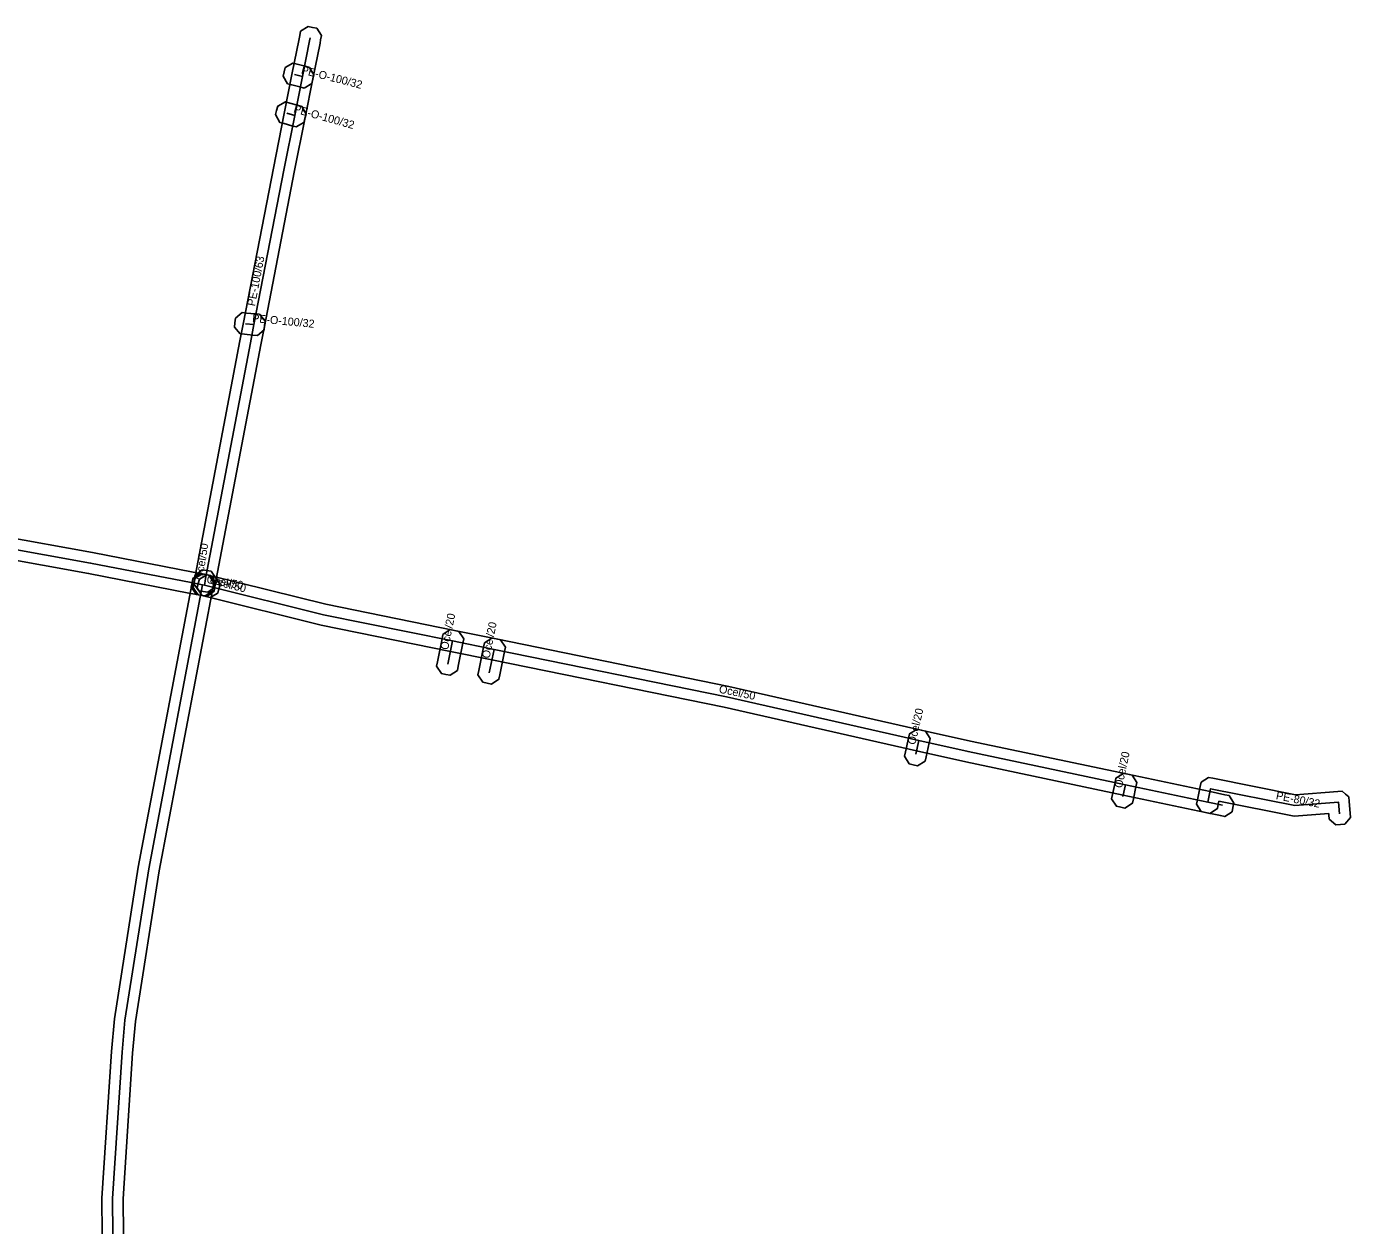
# Model space of a CAD drawing. Extents: x -569373 to -565022, y -1135090 to -1131496.
# Drawn here: x -566970.9 to -566846.8, y -1134085 to -1133972.5 of the extents above; entities that cross this region are included whole.
import ezdxf

# ---------------------------------------------------------------- set-up
doc = ezdxf.new("R2010")
doc.units = 0
for name, color, linetype in [('1', 7, 'Continuous'), ('24', 7, 'Continuous'), ('30', 7, 'Continuous')]:
    doc.layers.add(name, color=color, linetype=linetype)

msp = doc.modelspace()

# ---------------------------------------------------------------- linework, layer by layer
at = {"layer": '1'}
for points in [[(-566955.252, -1134024.771), (-566955.187, -1134024.362), (-566955.139, -1134024.062), (-566955.096, -1134023.897), (-566950.922, -1134001.992), (-566950.59, -1134000.272), (-566947.791, -1133985.798), (-566946.772, -1133980.668), (-566946.047, -1133977.022), (-566945.38, -1133973.671), (-566945.319, -1133973.377), (-566945.235, -1133972.971), (-566944.543, -1133972.517), (-566944.137, -1133972.601), (-566943.731, -1133972.685), (-566943.277, -1133973.377), (-566943.361, -1133973.783), (-566943.42, -1133974.069), (-566944.085, -1133977.412), (-566944.81, -1133981.058), (-566945.829, -1133986.182), (-566948.626, -1134000.652), (-566948.958, -1134002.368), (-566953.144, -1134024.343), (-566953.181, -1134024.478), (-566953.213, -1134024.678), (-566953.278, -1134025.087), (-566953.949, -1134025.572), (-566954.358, -1134025.507), (-566954.767, -1134025.442)], [(-566944.913, -1133978.289), (-566945.314, -1133978.186), (-566946.064, -1133977.994), (-566946.465, -1133977.891), (-566946.888, -1133977.178), (-566946.785, -1133976.777), (-566946.682, -1133976.376), (-566945.969, -1133975.953), (-566945.568, -1133976.056), (-566944.818, -1133976.248), (-566944.417, -1133976.351), (-566943.994, -1133977.064), (-566944.097, -1133977.465), (-566944.2, -1133977.866)], [(-566945.663, -1133981.938), (-566946.062, -1133981.826), (-566946.791, -1133981.621), (-566947.189, -1133981.509), (-566947.595, -1133980.786), (-566947.483, -1133980.387), (-566947.371, -1133979.989), (-566946.648, -1133979.583), (-566946.249, -1133979.695), (-566945.52, -1133979.9), (-566945.122, -1133980.012), (-566944.716, -1133980.735), (-566944.828, -1133981.134), (-566944.94, -1133981.532)], [(-566949.29, -1134001.497), (-566949.703, -1134001.458), (-566950.491, -1134001.383), (-566950.903, -1134001.344), (-566951.431, -1134000.705), (-566951.392, -1134000.292), (-566951.353, -1133999.88), (-566950.714, -1133999.352), (-566950.301, -1133999.391), (-566949.513, -1133999.466), (-566949.101, -1133999.505), (-566948.573, -1134000.144), (-566948.612, -1134000.557), (-566948.651, -1134000.969)], [(-566954.664, -1134023.813), (-566954.256, -1134023.885), (-566954.086, -1134023.915), (-566953.678, -1134023.987), (-566953.203, -1134024.666), (-566953.275, -1134025.074), (-566953.347, -1134025.482), (-566954.026, -1134025.957), (-566954.434, -1134025.885), (-566954.604, -1134025.855), (-566955.012, -1134025.783), (-566955.487, -1134025.104), (-566955.415, -1134024.696), (-566955.343, -1134024.288)], [(-566954.419, -1134023.829), (-566954.017, -1134023.93), (-566953.617, -1134024.03), (-566953.215, -1134024.13), (-566952.789, -1134024.841), (-566952.89, -1134025.243), (-566952.99, -1134025.645), (-566953.701, -1134026.071), (-566954.103, -1134025.97), (-566954.503, -1134025.87), (-566954.905, -1134025.77), (-566955.331, -1134025.059), (-566955.23, -1134024.657), (-566955.13, -1134024.255)], [(-566955.313, -1134025.153), (-566955.248, -1134024.744), (-566955.188, -1134024.364), (-566955.123, -1134023.955), (-566954.453, -1134023.467), (-566954.044, -1134023.532), (-566953.635, -1134023.597), (-566953.147, -1134024.267), (-566953.212, -1134024.676), (-566953.272, -1134025.056), (-566953.337, -1134025.465), (-566954.007, -1134025.953), (-566954.416, -1134025.888), (-566954.825, -1134025.823)], [(-566954.021, -1134023.93), (-566953.619, -1134024.03), (-566942.859, -1134026.704), (-566930.801, -1134029.16), (-566926.91, -1134029.95), (-566905.109, -1134034.402), (-566887.059, -1134038.495), (-566882.457, -1134039.533), (-566867.714, -1134042.642), (-566859.994, -1134044.271), (-566858.614, -1134044.561), (-566858.209, -1134044.646), (-566857.756, -1134045.34), (-566857.841, -1134045.746), (-566857.926, -1134046.151), (-566858.62, -1134046.604), (-566859.026, -1134046.519), (-566860.406, -1134046.229), (-566868.126, -1134044.598), (-566882.883, -1134041.487), (-566887.501, -1134040.445), (-566905.531, -1134036.358), (-566927.31, -1134031.91), (-566931.199, -1134031.12), (-566943.301, -1134028.656), (-566954.101, -1134025.97), (-566954.503, -1134025.87), (-566954.93, -1134025.161), (-566954.83, -1134024.759), (-566954.73, -1134024.357)], [(-566929.938, -1134029.934), (-566930.02, -1134030.34), (-566930.46, -1134032.5), (-566930.543, -1134032.906), (-566931.234, -1134033.362), (-566931.64, -1134033.28), (-566932.046, -1134033.197), (-566932.502, -1134032.506), (-566932.42, -1134032.1), (-566931.98, -1134029.94), (-566931.897, -1134029.534), (-566931.206, -1134029.078), (-566930.8, -1134029.16), (-566930.394, -1134029.243)], [(-566926.048, -1134030.721), (-566926.13, -1134031.127), (-566926.57, -1134033.317), (-566926.652, -1134033.723), (-566927.341, -1134034.182), (-566927.747, -1134034.1), (-566928.153, -1134034.018), (-566928.612, -1134033.329), (-566928.53, -1134032.923), (-566928.09, -1134030.733), (-566928.008, -1134030.327), (-566927.319, -1134029.868), (-566926.913, -1134029.95), (-566926.507, -1134030.032)], [(-566886.213, -1134039.291), (-566886.306, -1134039.695), (-566886.606, -1134040.995), (-566886.699, -1134041.398), (-566887.401, -1134041.837), (-566887.805, -1134041.744), (-566888.208, -1134041.651), (-566888.647, -1134040.949), (-566888.554, -1134040.545), (-566888.254, -1134039.245), (-566888.161, -1134038.842), (-566887.459, -1134038.403), (-566887.055, -1134038.496), (-566886.652, -1134038.589)], [(-566866.855, -1134043.425), (-566866.942, -1134043.83), (-566867.182, -1134044.95), (-566867.269, -1134045.355), (-566867.965, -1134045.805), (-566868.37, -1134045.718), (-566868.775, -1134045.631), (-566869.225, -1134044.935), (-566869.138, -1134044.53), (-566868.898, -1134043.41), (-566868.811, -1134043.005), (-566868.115, -1134042.555), (-566867.71, -1134042.642), (-566867.305, -1134042.729)], [(-566861.263, -1134045.452), (-566861.179, -1134045.046), (-566860.919, -1134043.796), (-566860.835, -1134043.393), (-566860.149, -1134042.939), (-566859.745, -1134043.019), (-566851.974, -1134044.565), (-566848.013, -1134044.262), (-566847.6, -1134044.23), (-566847.286, -1134044.5), (-566846.972, -1134044.77), (-566846.94, -1134045.183), (-566846.856, -1134046.28), (-566846.825, -1134046.693), (-566847.364, -1134047.322), (-566847.777, -1134047.353), (-566848.19, -1134047.384), (-566848.819, -1134046.845), (-566848.85, -1134046.432), (-566848.858, -1134046.332), (-566852.094, -1134046.581), (-566859.163, -1134045.174), (-566859.221, -1134045.454), (-566859.305, -1134045.86), (-566859.998, -1134046.313), (-566860.404, -1134046.229), (-566860.81, -1134046.145)]]:
    msp.add_lwpolyline(points, close=True, dxfattribs=at)
for points in [[(-566973.423, -1134020.286), (-566964.746, -1134021.847), (-566955.321, -1134023.678), (-566954.239, -1134023.888), (-566953.833, -1134023.967), (-566953.369, -1134024.654), (-566953.448, -1134025.061), (-566953.527, -1134025.467), (-566954.214, -1134025.931), (-566954.621, -1134025.852), (-566955.703, -1134025.642), (-566965.114, -1134023.813), (-566973.777, -1134022.254)], [(-566963.8, -1134089.13), (-566963.86, -1134082.402), (-566962.977, -1134068.622), (-566962.693, -1134065.576), (-566960.465, -1134051.34), (-566955.413, -1134024.684), (-566955.336, -1134024.277), (-566954.651, -1134023.81), (-566954.244, -1134023.887), (-566953.837, -1134023.964), (-566953.37, -1134024.649), (-566953.447, -1134025.056), (-566958.495, -1134051.68), (-566960.707, -1134065.824), (-566960.983, -1134068.778), (-566961.86, -1134082.458), (-566961.8, -1134089.11)]]:
    msp.add_lwpolyline(points, dxfattribs=at)
at = {"layer": '24'}
for points in [[(-566954.2, -1134024.52), (-566954.16, -1134024.27), (-566954.12, -1134024.12), (-566949.94, -1134002.18), (-566949.608, -1134000.462), (-566946.81, -1133985.99), (-566945.791, -1133980.863), (-566945.066, -1133977.217), (-566944.4, -1133973.87), (-566944.34, -1133973.58)], [(-566945.066, -1133977.217), (-566945.816, -1133977.025)], [(-566945.791, -1133980.863), (-566946.52, -1133980.658)], [(-566949.608, -1134000.462), (-566950.396, -1134000.387)], [(-567040.2, -1134008.68), (-567039.86, -1134008.72), (-567017.91, -1134013.16), (-567017.76, -1134013.19), (-567002.45, -1134016.23), (-566985.3, -1134019.2), (-566980.67, -1134020), (-566980.467, -1134020.036), (-566973.6, -1134021.27), (-566964.93, -1134022.83), (-566955.512, -1134024.66), (-566954.43, -1134024.87)], [(-566954.43, -1134024.87), (-566959.48, -1134051.51), (-566961.7, -1134065.7), (-566961.98, -1134068.7), (-566962.86, -1134082.43), (-566962.8, -1134089.12)], [(-566954.43, -1134024.87), (-566954.26, -1134024.9)], [(-566954.26, -1134024.9), (-566954.2, -1134024.52)], [(-566954.26, -1134024.9), (-566953.86, -1134025)], [(-566953.86, -1134025), (-566943.08, -1134027.68), (-566931, -1134030.14), (-566927.11, -1134030.93), (-566905.32, -1134035.38), (-566887.28, -1134039.47), (-566882.67, -1134040.51), (-566867.92, -1134043.62), (-566860.2, -1134045.25), (-566858.82, -1134045.54)], [(-566931, -1134030.14), (-566931.44, -1134032.3)], [(-566927.11, -1134030.93), (-566927.55, -1134033.12)], [(-566887.28, -1134039.47), (-566887.58, -1134040.77)], [(-566867.92, -1134043.62), (-566868.16, -1134044.74)], [(-566860.2, -1134045.25), (-566859.94, -1134044), (-566852.034, -1134045.573), (-566847.937, -1134045.259), (-566847.853, -1134046.356)]]:
    msp.add_lwpolyline(points, dxfattribs=at)

# ---------------------------------------------------------------- texts
at = {"layer": '30'}
for s, rotation, p in [('PE-O-100/32', 345.64066, (-566945.241, -1133976.921)), ('PE-O-100/32', 344.29364, (-566945.956, -1133980.561)), ('PE-100/63', 79.05751, (-566949.523, -1133998.789)), ('PE-O-100/32', 354.5631, (-566949.802, -1134000.225)), ('Ocel/50', 81.02737, (-566954.422, -1134024.461)), ('Ocel/50', 349.99202, (-566954.096, -1134024.694)), ('Ocel/50', 345.96376, (-566953.811, -1134024.762)), ('Ocel/20', 78.48617, (-566931.42, -1134031.02)), ('Ocel/20', 78.63976, (-566927.53, -1134031.825)), ('Ocel/50', 348.45765, (-566906.074, -1134034.985)), ('Ocel/20', 77.00538, (-566887.63, -1134039.92)), ('Ocel/20', 77.90524, (-566868.24, -1134043.98)), ('PE-80/32', 348.74722, (-566853.859, -1134044.97))]:
    msp.add_text(s, height=0.75, rotation=rotation, dxfattribs=at).set_placement(p)

doc.saveas('drawing.dxf')
